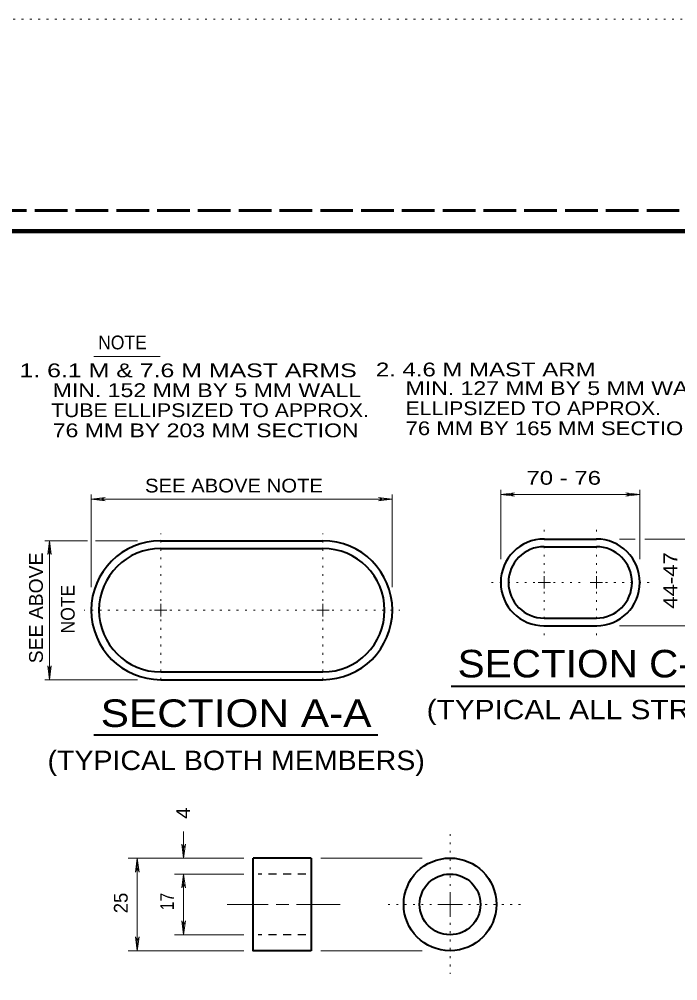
# Model space of a CAD drawing. Extents: x 312583 to 312854, y 144419 to 144597.
# Drawn here: x 312687.1 to 312723.4, y 144543.7 to 144596.8 of the extents above; entities that cross this region are included whole.
import ezdxf
from ezdxf.enums import TextEntityAlignment as Align

# ---------------------------------------------------------------- set-up
doc = ezdxf.new("R2010")
doc.units = 0
doc.header["$LTSCALE"] = 0.3
for name, pattern in [('DOTTED', [1.5, 0.3, -1.2]), ('LONG_DASHED', [7.5, 6, -1.5]), ('SHORT_DASHED', [2.7, 1.5, -1.2])]:
    doc.linetypes.add(name, pattern=pattern)
for name, color, linetype, lineweight in [('1', 7, 'Continuous', 13), ('62', 7, 'DOTTED', 13), ('63', 7, 'LONG_DASHED', 60)]:
    doc.layers.add(name, color=color, linetype=linetype, lineweight=lineweight)

msp = doc.modelspace()

# ---------------------------------------------------------------- linework, layer by layer
at = {"layer": '1'}
for p, q in [((312691.1992, 144578.1819), (312694.8562, 144578.1819)), ((312713.6518, 144566.9866), (312713.6518, 144570.8199)), ((312721.3185, 144566.9866), (312721.3185, 144570.8199)), ((312691.0643, 144565.459), (312691.0643, 144570.565)), ((312691.0643, 144570.312), (312691.831, 144570.404)), ((312691.0643, 144570.312), (312707.6703, 144570.312)), ((312691.0643, 144570.312), (312691.831, 144570.22)), ((312691.831, 144570.404), (312691.5857, 144570.312)), ((312691.831, 144570.22), (312691.5857, 144570.312)), ((312706.9037, 144570.404), (312707.149, 144570.312)), ((312707.6703, 144570.312), (312706.9037, 144570.404)), ((312706.9037, 144570.22), (312707.149, 144570.312)), ((312707.6703, 144570.312), (312706.9037, 144570.22)), ((312707.6703, 144565.459), (312707.6703, 144570.565)), ((312713.6518, 144570.5669), (312714.4185, 144570.6589)), ((312713.6518, 144570.5669), (312721.3185, 144570.5669)), ((312713.6518, 144570.5669), (312714.4185, 144570.4749)), ((312714.4185, 144570.6589), (312714.1731, 144570.5669)), ((312714.4185, 144570.4749), (312714.1731, 144570.5669)), ((312720.5518, 144570.6589), (312720.7971, 144570.5669)), ((312721.3185, 144570.5669), (312720.5518, 144570.6589)), ((312720.5518, 144570.4749), (312720.7971, 144570.5669)), ((312721.3185, 144570.5669), (312720.5518, 144570.4749)), ((312720.1991, 144568.1059), (312721.0731, 144568.1059)), ((312721.5945, 144568.1059), (312724.0325, 144568.1059)), ((312690.8573, 144568.012), (312688.5037, 144568.012)), ((312688.7643, 144568.012), (312688.6647, 144567.2453)), ((312688.7643, 144560.3453), (312688.7643, 144568.012)), ((312688.7643, 144568.012), (312688.8563, 144567.2453)), ((312693.6173, 144568.012), (312691.2943, 144568.012)), ((312688.6647, 144567.2453), (312688.7643, 144567.4907)), ((312688.8563, 144567.2453), (312688.7643, 144567.4907)), ((312716.0438, 144565.7139), (312716.0438, 144566.0512)), ((312718.9265, 144565.7139), (312718.9265, 144566.0512)), ((312716.0438, 144565.7139), (312715.7065, 144565.7139)), ((312716.0438, 144565.7139), (312716.3888, 144565.7139)), ((312716.0438, 144565.7139), (312716.0438, 144565.3689)), ((312718.9265, 144565.7139), (312718.5815, 144565.7139)), ((312718.9265, 144565.7139), (312719.2638, 144565.7139)), ((312718.9265, 144565.7139), (312718.9265, 144565.3689)), ((312694.8977, 144564.1787), (312694.8977, 144564.5237)), ((312703.837, 144564.1787), (312703.837, 144564.5237)), ((312694.8977, 144564.1787), (312694.5527, 144564.1787)), ((312694.8977, 144564.1787), (312695.235, 144564.1787)), ((312694.8977, 144564.1787), (312694.8977, 144563.8337)), ((312703.837, 144564.1787), (312703.4997, 144564.1787)), ((312703.837, 144564.1787), (312704.182, 144564.1787)), ((312703.837, 144564.1787), (312703.837, 144563.8337)), ((312720.1991, 144563.3142), (312724.0325, 144563.3142)), ((312688.6647, 144561.112), (312688.7643, 144560.8667)), ((312688.7643, 144560.3453), (312688.6647, 144561.112)), ((312688.8563, 144561.112), (312688.7643, 144560.8667)), ((312688.7643, 144560.3453), (312688.8563, 144561.112)), ((312693.6173, 144560.3453), (312688.5037, 144560.3453)), ((312696.157, 144550.5032), (312696.157, 144551.9743)), ((312696.065, 144551.2776), (312696.157, 144551.0322)), ((312696.157, 144550.5032), (312696.065, 144551.2776)), ((312696.2567, 144551.2776), (312696.157, 144551.0322)), ((312696.157, 144550.5032), (312696.2567, 144551.2776)), ((312699.4844, 144550.5032), (312693.0904, 144550.5032)), ((312693.604, 144550.5032), (312693.5044, 144549.7289)), ((312693.604, 144545.3896), (312693.604, 144550.5032)), ((312693.604, 144550.5032), (312693.7037, 144549.7289)), ((312703.7317, 144550.5032), (312709.3207, 144550.5032)), ((312693.5044, 144549.7289), (312693.604, 144549.9742)), ((312693.7037, 144549.7289), (312693.604, 144549.9742)), ((312699.4844, 144549.6216), (312695.651, 144549.6216)), ((312696.157, 144549.6216), (312696.065, 144548.8549)), ((312696.157, 144546.2712), (312696.157, 144549.6216)), ((312696.157, 144549.6216), (312696.2567, 144548.8549)), ((312696.065, 144548.8549), (312696.157, 144549.1002)), ((312696.2567, 144548.8549), (312696.157, 144549.1002)), ((312710.854, 144547.9502), (312710.854, 144548.6249)), ((312700.826, 144547.9502), (312698.5644, 144547.9502)), ((312701.953, 144547.9502), (312701.263, 144547.9502)), ((312702.39, 144547.9502), (312704.7974, 144547.9502)), ((312710.854, 144547.9502), (312710.1717, 144547.9502)), ((312710.854, 144547.9502), (312711.5364, 144547.9502)), ((312710.854, 144547.9502), (312710.854, 144547.2679)), ((312696.065, 144547.0456), (312696.157, 144546.8002)), ((312696.157, 144546.2712), (312696.065, 144547.0456)), ((312696.2567, 144547.0456), (312696.157, 144546.8002)), ((312696.157, 144546.2712), (312696.2567, 144547.0456)), ((312693.5044, 144546.1639), (312693.604, 144545.9186)), ((312693.604, 144545.3896), (312693.5044, 144546.1639)), ((312693.7037, 144546.1639), (312693.604, 144545.9186)), ((312693.604, 144545.3896), (312693.7037, 144546.1639)), ((312699.4844, 144546.2712), (312695.651, 144546.2712)), ((312699.4844, 144545.3896), (312693.0904, 144545.3896)), ((312703.7317, 144545.3896), (312709.3207, 144545.3896))]:
    msp.add_line(p, q, dxfattribs=at)
at = {"layer": '1', "linetype": 'DOTTED'}
for p, q in [((312716.0438, 144566.2199), (312716.0438, 144568.7959)), ((312718.9265, 144566.2199), (312718.9265, 144568.7959)), ((312694.8977, 144564.6923), (312694.8977, 144568.403)), ((312703.837, 144564.6923), (312703.837, 144568.403)), ((312715.5378, 144565.7139), (312712.9235, 144565.7139)), ((312716.5575, 144565.7139), (312718.3821, 144565.7139)), ((312719.4325, 144565.7139), (312721.9471, 144565.7139)), ((312716.0438, 144565.2002), (312716.0438, 144562.5169)), ((312718.9265, 144565.2002), (312718.9265, 144562.5169)), ((312694.384, 144564.1787), (312690.6733, 144564.1787)), ((312695.4037, 144564.1787), (312703.331, 144564.1787)), ((312704.3507, 144564.1787), (312708.0767, 144564.1787)), ((312694.8977, 144563.665), (312694.8977, 144560.0233)), ((312703.837, 144563.665), (312703.837, 144560.0233)), ((312710.854, 144548.9699), (312710.854, 144551.9216)), ((312709.8344, 144547.9502), (312707.3197, 144547.9502)), ((312711.8737, 144547.9502), (312714.856, 144547.9502)), ((312710.854, 144546.9229), (312710.854, 144544.1246))]:
    msp.add_line(p, q, dxfattribs=at)
at = {"layer": '1', "lineweight": 40}
for p, q in [((312716.0438, 144568.1059), (312718.9265, 144568.1059)), ((312694.8977, 144568.012), (312703.837, 144568.012)), ((312694.8977, 144567.5827), (312703.837, 144567.5827)), ((312716.0438, 144567.6842), (312718.9265, 144567.6842)), ((312716.0438, 144563.7436), (312718.9265, 144563.7436)), ((312716.0438, 144563.3142), (312718.9265, 144563.3142)), ((312694.8977, 144560.7747), (312703.837, 144560.7747)), ((312694.8977, 144560.3453), (312703.837, 144560.3453)), ((312710.9077, 144559.989), (312726.3126, 144559.989)), ((312691.2057, 144557.2939), (312706.868, 144557.2939)), ((312703.1874, 144550.5032), (312699.9904, 144550.5032)), ((312703.1874, 144550.5032), (312703.1874, 144545.3896))]:
    msp.add_line(p, q, dxfattribs=at)
at = {"layer": '1', "linetype": 'SHORT_DASHED', "lineweight": 25}
for p, q in [((312702.9037, 144549.6216), (312700.274, 144549.6216)), ((312702.9037, 144546.2712), (312700.274, 144546.2712))]:
    msp.add_line(p, q, dxfattribs=at)
at = {"layer": '1', "lineweight": 158}
msp.add_lwpolyline([(312616.5, 144423.1446), (312616.5, 144585.0846), (312849, 144585.0846)], dxfattribs=at)
at = {"layer": '1', "lineweight": 40}
msp.add_lwpolyline([(312703.1874, 144545.3896), (312699.9904, 144545.3896), (312699.9904, 144550.5032)], dxfattribs=at)
for radius in [2.5556, 1.6764]:
    msp.add_circle((312710.854, 144547.9477), radius, dxfattribs=at)
for centre, radius, start, end in [((312716.0464, 144565.7113), 2.3958, 90, 270), ((312718.9239, 144565.7113), 2.3958, 270, 90), ((312694.8951, 144564.1787), 3.8333, 90, 270), ((312694.8951, 144564.1787), 3.4066, 90, 270), ((312703.8396, 144564.1787), 3.8333, 270, 90), ((312703.8396, 144564.1787), 3.4066, 270, 90), ((312716.0464, 144565.7113), 1.9699, 90, 270), ((312718.9239, 144565.7113), 1.9699, 270, 90)]:
    msp.add_arc(centre, radius, start, end, dxfattribs=at)
at = {"layer": '62'}
msp.add_line((312601.2, 144596.7846), (312853.5, 144596.7846), dxfattribs=at)
at = {"layer": '63'}
msp.add_line((312851.75, 144586.2246), (312583.526, 144586.2246), dxfattribs=at)

# ---------------------------------------------------------------- texts
at = {"layer": '1'}
for s, height, width, p in [('NOTE', 0.76, 0.95, (312691.444, 144578.5713)), ('1. 6.1 M & 7.6 M MAST ARMS', 0.76, 1.35, (312687.1035, 144577.0305)), ('2. 4.6 M MAST ARM', 0.76, 1.3, (312706.7644, 144577.0804)), ('MIN. 152 MM BY 5 MM WALL ', 0.76, 1.25, (312688.9375, 144575.9371)), ('MIN. 127 MM BY 5 MM WALL TUBE', 0.76, 1.25, (312708.4015, 144576.0521)), ('TUBE ELLIPSIZED TO APPROX.', 0.76, 1.15, (312688.8455, 144574.8331)), ('ELLIPSIZED TO APPROX.', 0.76, 1.15, (312708.4015, 144574.9405)), ('76 MM BY 203 MM SECTION', 0.76, 1.25, (312688.9375, 144573.7215)), ('76 MM BY 165 MM SECTION', 0.76, 1.2, (312708.4015, 144573.8365)), ('70 - 76 ', 0.76, 1.3, (312715.0668, 144571.1017)), ('SEE ABOVE NOTE', 0.76, 1.1, (312694.0281, 144570.6744)), ('SECTION C-C', 1.52, 1.1, (312711.2732, 144560.4701)), ('SECTION A-A', 1.52, 1.15, (312691.5836, 144557.7369))]:
    msp.add_text(s, height=height, dxfattribs=dict(at, width=width)).set_placement(p)
for s, width, p in [('SEE ABOVE', 1.05, (312688.3932, 144561.2497)), ('44-47', 1.2, (312723.3871, 144564.2595)), ('NOTE', 0.95, (312690.147, 144562.8976)), ('4 ', 1.1, (312696.5185, 144552.6688)), ('17', 0.85, (312695.6248, 144547.6276))]:
    msp.add_text(s, height=0.76, rotation=90, dxfattribs=dict(at, width=width)).set_placement(p)
for s, width, p in [('(TYPICAL ALL STRUTS)', 1.15, (312718.7514, 144558.1626)), ('(TYPICAL BOTH MEMBERS)', 1.1, (312699.0567, 144555.3584))]:
    msp.add_text(s, height=1.07, dxfattribs=dict(at, width=width)).set_placement(p, align=Align.CENTER)
msp.add_text('25', height=0.76, rotation=90, dxfattribs=at).set_placement((312693.0718, 144547.46))

doc.saveas('drawing.dxf')
